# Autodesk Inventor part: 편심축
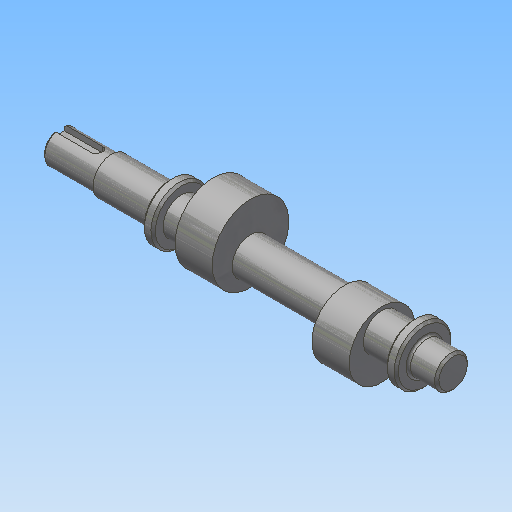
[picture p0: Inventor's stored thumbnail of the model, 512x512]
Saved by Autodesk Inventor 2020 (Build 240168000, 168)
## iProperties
Created: 2021-06
Part Number: 편심축
Material: 강철, 연강
Document SubType Name: Modeling
Designer: mdu-edu
Density: 7.86 g/cm^3
Appearance: 강철
Author: mdu-edu
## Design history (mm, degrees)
sketch "스케치1"
  geometry: L1 (0, 0)-(180, 0); L2 (180, 0)-(180, -7.5); L3 (180, -7.5)-(167, -7.5); L4 (167, -7.5)-(167, -13); L5 (167, -13)-(162, -13); L6 (162, -13)-(162, -8.5); L7 (162, -8.5)-(56, -8.5); L8 (56, -8.5)-(56, -13); L9 (56, -13)-(51, -13); L10 (51, -13)-(51, -8.5); L11 (51, -8.5)-(24, -8.5); L12 (24, -8.5)-(24, -7.5); L13 (24, -7.5)-(0, -7.5); L14 (0, -7.5)-(0, 0)
  constraints: 28 end point, 6 parallel, 3 horizontal, 3 vertical, 1 collinear, 1 perpendicular
  dimensions: "d0" = 15 diameter of L13 L1; "d2" = 26 diameter of L9 L1; "d3" = 26 diameter of L5 L1; "d4" = 15 diameter of L3 L1; "d5" = 17 diameter of L7 L1; "d6" = 17 diameter of L11 L1; "d7" = 24 distance between parallel lines of L12 L14; "d8" = 51 distance between parallel lines of L14 L10; "d10" = 5 distance of L8.end L9.end; "d11" = 5 distance of L4.end L5.end; "d12" = 13 distance between parallel lines of L4 L2; "d13" = 180 distance between parallel lines of L14 L2
revolve "회전1" sketch "스케치1" stored, may be unused: angle "d14" = 90 deg
node "작업 평면1"
sketch "스케치2"
  geometry: C1 r 17.5 at (0, 5); 1 further point
  constraints: 1 centre point, 1 vertical alignment
  dimensions: "d16" = 35 diameter of C1; "d17" = 5 distance of C1.centre point (0, 0)
extrude "돌출1" join sketch "스케치2" distance "d18" = 17; taper "d19" = 0 deg
node "작업 평면2"
sketch "스케치3"
  geometry: C1 r 15 at (0, -5); 1 further point
  constraints: 1 centre point, 1 vertical alignment
  dimensions: "d21" = 30 diameter of C1; "d22" = 5 distance of point (0, 0) C1.centre
extrude "돌출2" join sketch "스케치3" distance "d23" = 17; taper "d24" = 0 deg
chamfer "모따기1" distance "d29" = 1; stored, may be unused: second distance "d30" = 2, angle "d31" = 45 deg
node "작업 평면3"
sketch "스케치4"
  geometry: L1 (-5.5, 2.5)-(12, 2.5); L2 (12, 2.5)-(12, -2.5); L3 (12, -2.5)-(-5.5, -2.5); L4 (12, 6.5)-(12, -6.5) reference; A1 r 2.5 centre (-5.5, 0) between (-5.5, 2.5) and (-5.5, -2.5); 1 further point
  constraints: 6 end point, 2 point on circle, 2 tangent, 1 centre point, 1 collinear, 1 horizontal, 1 horizontal alignment, 1 midpoint, 1 parallel, 1 perpendicular
  dimensions: "d25" = 5 diameter of A1; "d32" = 20 dimension on A1 L4
extrude "돌출3" cut sketch "스케치4" distance "d27" = 3; taper "d28" = 0 deg
fillet "모깎기1" dims "d33" = 0.6
fillet "모깎기2" dims "d34" = 1
node "솔리드1"
other parameters: "d15" = -70.5, "d20" = -32.5
